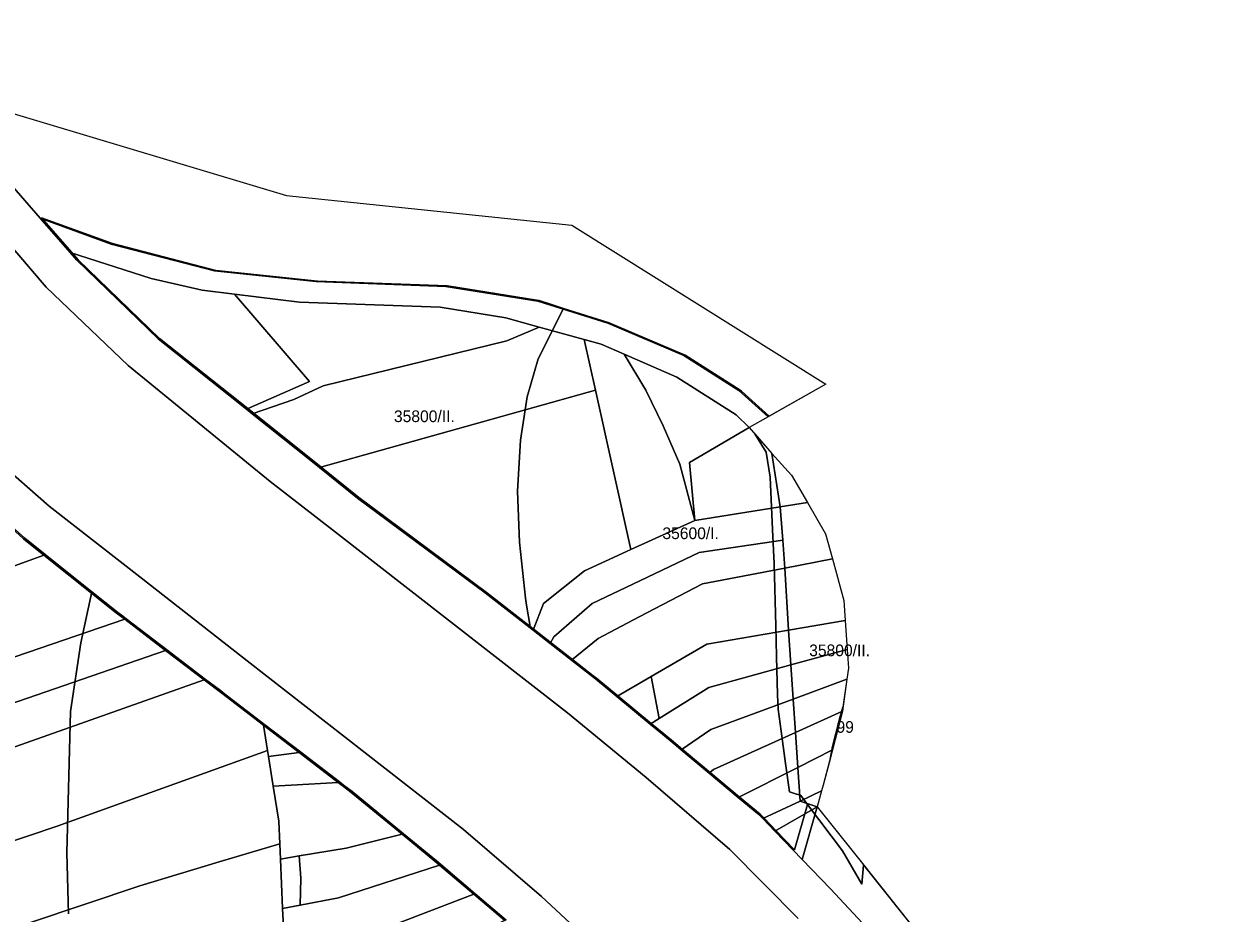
# Model space of a CAD drawing. Extents: x -535894 to -532834, y -1165802 to -1163645.
# Drawn here: x -533625 to -533117, y -1164507 to -1164127 of the extents above; entities that cross this region are included whole.
import ezdxf

# ---------------------------------------------------------------- set-up
doc = ezdxf.new("R2010")
doc.units = 0
for name, color, linetype in [('95560013', 7, 'Continuous'), ('95610013', 7, 'Continuous'), ('95630013', 7, 'Continuous'), ('95640013', 7, 'Continuous'), ('95660013', 7, 'Continuous')]:
    doc.layers.add(name, color=color, linetype=linetype)

msp = doc.modelspace()

# ---------------------------------------------------------------- linework, layer by layer
at = {"layer": '95560013'}
for points in [[(-533605.59, -1164224.96), (-533571.03, -1164236.07), (-533549.12, -1164240.98), (-533535.33, -1164242.69), (-533503.3, -1164280.07), (-533530.25, -1164291.87), (-533567.95, -1164261.82), (-533602.74, -1164228.22)], [(-533507.55, -1164246.14), (-533447.47, -1164248.27), (-533419.39, -1164252.85), (-533405.05, -1164256.81), (-533418.99, -1164262.66), (-533497.49, -1164281.99), (-533509.99, -1164287.71), (-533527.78, -1164293.84), (-533530.25, -1164291.87), (-533503.3, -1164280.07), (-533535.33, -1164242.69)], [(-533385.83, -1164262.11), (-533381.03, -1164283.8), (-533498.95, -1164316.9), (-533508.97, -1164308.83), (-533527.78, -1164293.84), (-533509.99, -1164287.71), (-533497.49, -1164281.99), (-533418.99, -1164262.66), (-533405.05, -1164256.81)], [(-533378.64, -1164264.1), (-533368.79, -1164268.38), (-533359.57, -1164283.78), (-533352.12, -1164299.01), (-533345.01, -1164315.49), (-533338.55, -1164339.54), (-533365.92, -1164351.97), (-533381.03, -1164283.8), (-533385.83, -1164262.11)], [(-533346.28, -1164278.18), (-533320.95, -1164294.31), (-533315.38, -1164299.76), (-533340.84, -1164314.67), (-533338.55, -1164339.54), (-533345.01, -1164315.49), (-533352.12, -1164299.01), (-533359.57, -1164283.78), (-533368.79, -1164268.38)], [(-533498.95, -1164316.9), (-533381.03, -1164283.8), (-533365.92, -1164351.97), (-533367.81, -1164352.83), (-533385.8, -1164361), (-533403.21, -1164375.02), (-533407.7, -1164386.45), (-533428.16, -1164370.44), (-533482.76, -1164329.92)], [(-533305.71, -1164310.91), (-533302.09, -1164333.74), (-533338.55, -1164339.54), (-533340.84, -1164314.67), (-533315.38, -1164299.76)], [(-533305.71, -1164310.91), (-533297.21, -1164320.14), (-533290.4, -1164331.87), (-533302.09, -1164333.74)], [(-533338.55, -1164339.54), (-533302.09, -1164333.74), (-533300.97, -1164347.97), (-533336.72, -1164353.24), (-533365.08, -1164366.74), (-533382.4, -1164374.97), (-533398.87, -1164389.28), (-533400.38, -1164392.18), (-533407.7, -1164386.45), (-533403.21, -1164375.02), (-533385.8, -1164361), (-533367.81, -1164352.83), (-533365.92, -1164351.97)], [(-533302.09, -1164333.74), (-533290.4, -1164331.87), (-533282.74, -1164345.28), (-533279.76, -1164355.99), (-533300.16, -1164359.88), (-533300.97, -1164347.97)], [(-533632.43, -1164341.14), (-533625.55, -1164347.3), (-533616.81, -1164354.28), (-533723.42, -1164393.06), (-533771.52, -1164411.45), (-533810.55, -1164423.74), (-533962.73, -1164479.54), (-533965.5, -1164468.47), (-533967.42, -1164462.17), (-533868.12, -1164425.2)], [(-533336.72, -1164353.24), (-533300.97, -1164347.97), (-533300.16, -1164359.88), (-533335.3, -1164366.6), (-533362.32, -1164380.78), (-533379.89, -1164389.99), (-533391.36, -1164399.24), (-533400.38, -1164392.18), (-533398.87, -1164389.28), (-533382.4, -1164374.97), (-533365.08, -1164366.74)], [(-533616.81, -1164354.28), (-533585.87, -1164379.01), (-533582.28, -1164381.75), (-533655.23, -1164406.66), (-533798.86, -1164459.07), (-533954.44, -1164514.16), (-533955.24, -1164509.41), (-533962.73, -1164479.54), (-533810.55, -1164423.74), (-533771.52, -1164411.45), (-533723.42, -1164393.06)], [(-533335.3, -1164366.6), (-533300.16, -1164359.88), (-533298.54, -1164386.42), (-533333.5, -1164392.41), (-533357.3, -1164406.29), (-533371.94, -1164414.84), (-533381.09, -1164407.28), (-533391.36, -1164399.24), (-533379.89, -1164389.99), (-533362.32, -1164380.78)], [(-533300.16, -1164359.88), (-533279.76, -1164355.99), (-533274.89, -1164373.76), (-533274.29, -1164382.26), (-533298.54, -1164386.42)], [(-533582.28, -1164381.75), (-533564.8, -1164395.06), (-533671.49, -1164431.9), (-533847.42, -1164496.13), (-533951.43, -1164531.95), (-533954.44, -1164514.16), (-533798.86, -1164459.07), (-533655.23, -1164406.66)], [(-533298.54, -1164386.42), (-533274.29, -1164382.26), (-533273.41, -1164394.65), (-533297.5, -1164401.27)], [(-533333.5, -1164392.41), (-533298.54, -1164386.42), (-533297.5, -1164401.27), (-533332.56, -1164410.91), (-533353.78, -1164424.22), (-533357.3, -1164406.29)], [(-533564.8, -1164395.06), (-533548.26, -1164407.66), (-533732.91, -1164473.02), (-533829.26, -1164508.78), (-533948.58, -1164548.78), (-533951.43, -1164531.95), (-533847.42, -1164496.13), (-533671.49, -1164431.9)], [(-533297.5, -1164401.27), (-533273.41, -1164394.65), (-533272.85, -1164402.66), (-533273.53, -1164407.35), (-533296.57, -1164415.9)], [(-533332.56, -1164410.91), (-533297.5, -1164401.27), (-533296.57, -1164415.9), (-533331.75, -1164428.95), (-533344.43, -1164437.59), (-533347.48, -1164435.05), (-533352.45, -1164430.94), (-533357.65, -1164426.65), (-533353.78, -1164424.22)], [(-533371.94, -1164414.84), (-533357.3, -1164406.29), (-533353.78, -1164424.22), (-533357.65, -1164426.65)], [(-533548.26, -1164407.66), (-533540.77, -1164413.38), (-533522.97, -1164427.03), (-533521.25, -1164437.9), (-533611.16, -1164470.19), (-533698.34, -1164499.57), (-533834.24, -1164549.38), (-533941.27, -1164585.42), (-533948.58, -1164548.78), (-533829.26, -1164508.78), (-533732.91, -1164473.02)], [(-533296.57, -1164415.9), (-533273.53, -1164407.35), (-533275.5, -1164421.12), (-533295.61, -1164430.22)], [(-533331.75, -1164428.95), (-533296.57, -1164415.9), (-533295.61, -1164430.22), (-533330.63, -1164446.04), (-533332.48, -1164447.55), (-533344.43, -1164437.59)], [(-533295.61, -1164430.22), (-533275.5, -1164421.12), (-533279.71, -1164437.57), (-533294.57, -1164445.09)], [(-533521.25, -1164437.9), (-533522.97, -1164427.03), (-533507.65, -1164438.78), (-533520.85, -1164440.43)], [(-533295.61, -1164430.22), (-533294.57, -1164445.09), (-533320, -1164457.95), (-533332.48, -1164447.55), (-533330.63, -1164446.04)], [(-533520.85, -1164440.43), (-533518.84, -1164453.12), (-533516.47, -1164468.06), (-533516.03, -1164477.8), (-533541.84, -1164485.53), (-533575.81, -1164495.71), (-533694.14, -1164535.35), (-533849.54, -1164592.24), (-533906.52, -1164610.42), (-533945.61, -1164619.41), (-533941.56, -1164587.64), (-533941.27, -1164585.42), (-533834.24, -1164549.38), (-533698.34, -1164499.57), (-533611.16, -1164470.19), (-533521.25, -1164437.9)], [(-533520.85, -1164440.43), (-533507.65, -1164438.78), (-533491.1, -1164451.5), (-533511.14, -1164452.67), (-533518.84, -1164453.12)], [(-533294.57, -1164445.09), (-533279.71, -1164437.57), (-533283.68, -1164452.7), (-533284.39, -1164455.19), (-533293.51, -1164459.56)], [(-533320, -1164457.95), (-533294.57, -1164445.09), (-533293.51, -1164459.56), (-533309.57, -1164466.99), (-533311.26, -1164465.24)], [(-533511.14, -1164452.67), (-533491.1, -1164451.5), (-533489.36, -1164452.83), (-533485.66, -1164455.66), (-533463.74, -1164473.66), (-533487.58, -1164479.72), (-533507.75, -1164482.99), (-533515.75, -1164484.29), (-533516.03, -1164477.8), (-533516.47, -1164468.06), (-533518.84, -1164453.12)], [(-533293.51, -1164459.56), (-533284.39, -1164455.19), (-533286.31, -1164461.99)], [(-533293.51, -1164459.56), (-533286.31, -1164461.99), (-533304.36, -1164472.39), (-533309.57, -1164466.99)], [(-533304.36, -1164472.39), (-533286.31, -1164461.99), (-533292.65, -1164484.53)], [(-533487.58, -1164479.72), (-533463.74, -1164473.66), (-533449.65, -1164485.24), (-533447.72, -1164486.86), (-533490.83, -1164500.89), (-533507.3, -1164504.04), (-533507.02, -1164492.54), (-533507.75, -1164482.99)], [(-533515.75, -1164484.29), (-533514.81, -1164505.48), (-533514.33, -1164516.05), (-533539.69, -1164523.07), (-533562.86, -1164529.48), (-533603.27, -1164541.66), (-533709.08, -1164577.64), (-533811.93, -1164617.39), (-533884.44, -1164639.64), (-533944.79, -1164655.52), (-533945.09, -1164650.16), (-533945.65, -1164648.02), (-533949.17, -1164647.34), (-533948.72, -1164643.84), (-533945.61, -1164619.41), (-533906.52, -1164610.42), (-533849.54, -1164592.24), (-533694.14, -1164535.35), (-533575.81, -1164495.71), (-533541.84, -1164485.53), (-533516.03, -1164477.8)], [(-533515.75, -1164484.29), (-533507.75, -1164482.99), (-533507.02, -1164492.54), (-533507.3, -1164504.04), (-533514.81, -1164505.48)], [(-533447.72, -1164486.86), (-533433.01, -1164499.36), (-533492.42, -1164522.13), (-533506.35, -1164525.6), (-533512.72, -1164527.18), (-533514.33, -1164516.05), (-533514.81, -1164505.48), (-533507.3, -1164504.04), (-533490.83, -1164500.89)], [(-533433.01, -1164499.36), (-533419.75, -1164510.6), (-533455.4, -1164526.78), (-533503.24, -1164545.82), (-533509.63, -1164548.37), (-533511.85, -1164533.08), (-533512.72, -1164527.18), (-533506.35, -1164525.6), (-533492.42, -1164522.13)]]:
    msp.add_lwpolyline(points, close=True, dxfattribs=at)
at = {"layer": '95610013'}
msp.add_lwpolyline([(-533588.04, -1164221.3), (-533543.95, -1164232.77), (-533500.45, -1164237.33), (-533445.02, -1164239.39), (-533405.72, -1164245.67), (-533375.76, -1164255.2), (-533343.32, -1164268.94), (-533319.79, -1164283.92), (-533307.29, -1164295.19), (-533315.38, -1164299.76), (-533320.95, -1164294.31), (-533346.28, -1164278.18), (-533368.79, -1164268.38), (-533378.64, -1164264.1), (-533385.83, -1164262.11), (-533405.05, -1164256.81), (-533419.39, -1164252.85), (-533447.47, -1164248.27), (-533507.55, -1164246.14), (-533535.33, -1164242.69), (-533549.12, -1164240.98), (-533571.03, -1164236.07), (-533605.59, -1164224.96), (-533618.43, -1164210.24)], close=True, dxfattribs=at)
at = {"layer": '95630013'}
msp.add_lwpolyline([(-533663.1, -1164153.72), (-533678.92, -1164127.1), (-533637.25, -1164163.31), (-533513.14, -1164200.59), (-533391.15, -1164213.21), (-533282.63, -1164281.27), (-533307.29, -1164295.19), (-533319.79, -1164283.92), (-533343.32, -1164268.94), (-533375.76, -1164255.2), (-533405.72, -1164245.67), (-533445.02, -1164239.39), (-533500.45, -1164237.33), (-533543.95, -1164232.77), (-533588.04, -1164221.3), (-533618.43, -1164210.24), (-533640.06, -1164185.46)], close=True, dxfattribs=at)
for points in [[(-533652.75, -1164196.64), (-533615.89, -1164239.81), (-533580.88, -1164273.2), (-533520.08, -1164322.87), (-533493.52, -1164343.51), (-533393.01, -1164421.73), (-533359.31, -1164449.39), (-533323.6, -1164480.19), (-533294.45, -1164509.67)], [(-533365.03, -1164536.67), (-533404.17, -1164500.26), (-533437.52, -1164471.63), (-533529.97, -1164399.56), (-533574.57, -1164364.55), (-533614.65, -1164333.34), (-533637.12, -1164313.74)]]:
    msp.add_lwpolyline(points, dxfattribs=at)
at = {"layer": '95640013'}
for points in [[(-533640.06, -1164185.46), (-533618.43, -1164210.24), (-533605.59, -1164224.96), (-533602.74, -1164228.22), (-533567.95, -1164261.82), (-533530.25, -1164291.87), (-533527.78, -1164293.84), (-533508.97, -1164308.83), (-533498.95, -1164316.9), (-533482.76, -1164329.92), (-533428.16, -1164370.44), (-533407.7, -1164386.45), (-533400.38, -1164392.18), (-533391.36, -1164399.24), (-533381.09, -1164407.28), (-533371.94, -1164414.84), (-533357.65, -1164426.65), (-533352.45, -1164430.94), (-533347.48, -1164435.05), (-533344.43, -1164437.59), (-533332.48, -1164447.55), (-533320, -1164457.95), (-533311.26, -1164465.24), (-533309.57, -1164466.99), (-533304.36, -1164472.39), (-533292.65, -1164484.53), (-533280.62, -1164497.03), (-533235.68, -1164545.17)], [(-533294.45, -1164509.67), (-533323.6, -1164480.19), (-533359.31, -1164449.39), (-533393.01, -1164421.73), (-533493.52, -1164343.51), (-533520.08, -1164322.87), (-533580.88, -1164273.2), (-533615.89, -1164239.81), (-533652.75, -1164196.64)], [(-533637.12, -1164313.74), (-533614.65, -1164333.34), (-533574.57, -1164364.55), (-533529.97, -1164399.56), (-533437.52, -1164471.63), (-533404.17, -1164500.26), (-533365.03, -1164536.67)], [(-533419.75, -1164510.6), (-533433.01, -1164499.36), (-533447.72, -1164486.86), (-533449.65, -1164485.24), (-533463.74, -1164473.66), (-533485.66, -1164455.66), (-533489.36, -1164452.83), (-533491.1, -1164451.5), (-533507.65, -1164438.78), (-533522.97, -1164427.03), (-533540.77, -1164413.38), (-533548.26, -1164407.66), (-533564.8, -1164395.06), (-533582.28, -1164381.75), (-533585.87, -1164379.01), (-533616.81, -1164354.28), (-533625.55, -1164347.3)]]:
    msp.add_lwpolyline(points, dxfattribs=at)
msp.add_lwpolyline([(-533286.31, -1164461.99), (-533266.97, -1164486.26), (-533227.22, -1164536.15), (-533217.69, -1164548.05), (-533212.4, -1164563.33), (-533202.85, -1164583.35), (-533177.04, -1164603.82), (-533165.64, -1164607.65), (-533127.31, -1164620.51), (-533116.98, -1164633.6), (-533177.92, -1164613.75), (-533205.86, -1164580.27), (-533235.68, -1164545.17), (-533280.62, -1164497.03), (-533292.65, -1164484.53)], close=True, dxfattribs=at)
at = {"layer": '95660013'}
for points in [[(-533637.25, -1164163.31), (-533513.14, -1164200.59), (-533391.15, -1164213.21), (-533282.63, -1164281.27), (-533306.824, -1164294.927), (-533318.689, -1164284.23), (-533319.215, -1164283.756), (-533342.741, -1164268.774), (-533364.507, -1164259.557), (-533375.189, -1164255.034), (-533394.693, -1164248.828), (-533399.775, -1164247.211), (-533405.147, -1164245.502), (-533406.3, -1164245.318), (-533439.891, -1164239.947), (-533444.45, -1164239.218), (-533499.877, -1164237.155), (-533543.375, -1164232.587), (-533587.465, -1164221.122), (-533617.855, -1164210.054), (-533605.015, -1164224.773), (-533602.168, -1164228.037), (-533567.381, -1164261.637), (-533529.675, -1164291.688), (-533508.391, -1164308.653), (-533498.372, -1164316.72), (-533482.183, -1164329.739), (-533427.582, -1164370.261), (-533408.962, -1164384.837), (-533407.119, -1164386.28), (-533399.797, -1164392.005), (-533390.783, -1164399.064), (-533382.023, -1164405.923), (-533380.51, -1164407.108), (-533371.36, -1164414.666), (-533357.069, -1164426.477), (-533351.871, -1164430.767), (-533346.896, -1164434.883), (-533343.848, -1164437.415), (-533331.897, -1164447.377), (-533319.421, -1164457.779), (-533310.674, -1164465.071), (-533308.987, -1164466.818), (-533303.773, -1164472.227), (-533295.97, -1164480.319), (-533290.471, -1164460.99), (-533275.469, -1164480.798), (-533267.177, -1164495.052), (-533266.414, -1164486.957), (-533227.22, -1164536.15)], [(-533631.849, -1164340.954), (-533624.977, -1164347.111), (-533616.237, -1164354.099), (-533596.317, -1164370.019), (-533601.09, -1164391.8), (-533605.391, -1164421.259), (-533606.98, -1164481.63), (-533606.34, -1164507.75)], [(-533419.163, -1164510.425), (-533432.421, -1164499.181), (-533447.139, -1164486.688), (-533449.061, -1164485.066), (-533463.157, -1164473.487), (-533485.08, -1164455.484), (-533488.779, -1164452.648), (-533490.512, -1164451.319), (-533507.067, -1164438.601), (-533522.39, -1164426.846), (-533540.189, -1164413.195), (-533541.383, -1164412.285), (-533547.683, -1164407.482), (-533564.22, -1164394.878), (-533581.704, -1164381.564), (-533583.679, -1164380.059), (-533585.293, -1164378.83), (-533596.317, -1164370.019), (-533616.237, -1164354.099), (-533624.977, -1164347.111), (-533631.849, -1164340.954)], [(-533606.34, -1164507.75), (-533606.98, -1164481.63), (-533605.391, -1164421.259), (-533601.09, -1164391.8), (-533596.317, -1164370.019), (-533585.293, -1164378.83), (-533583.679, -1164380.059), (-533581.704, -1164381.564), (-533564.22, -1164394.878), (-533547.683, -1164407.482), (-533541.383, -1164412.285), (-533540.189, -1164413.195), (-533522.39, -1164426.846), (-533507.067, -1164438.601), (-533490.512, -1164451.319), (-533488.779, -1164452.648), (-533485.08, -1164455.484), (-533463.157, -1164473.487), (-533449.061, -1164485.066), (-533447.139, -1164486.688), (-533432.421, -1164499.181), (-533419.163, -1164510.425)]]:
    msp.add_lwpolyline(points, dxfattribs=at)
for points in [[(-533394.693, -1164248.828), (-533405.49, -1164270.43), (-533410.27, -1164286.67), (-533413.14, -1164305.15), (-533414.411, -1164326.97), (-533413.524, -1164348.809), (-533410.92, -1164372.686), (-533410.59, -1164375.71), (-533408.962, -1164384.837), (-533427.582, -1164370.261), (-533482.183, -1164329.739), (-533498.372, -1164316.72), (-533508.391, -1164308.653), (-533529.675, -1164291.688), (-533567.381, -1164261.637), (-533602.168, -1164228.037), (-533605.015, -1164224.773), (-533617.855, -1164210.054), (-533587.465, -1164221.122), (-533543.375, -1164232.587), (-533499.877, -1164237.155), (-533444.45, -1164239.218), (-533439.891, -1164239.947), (-533406.3, -1164245.318), (-533405.147, -1164245.502), (-533399.775, -1164247.211)], [(-533306.824, -1164294.927), (-533307.29, -1164295.19), (-533315.38, -1164299.76), (-533312.979, -1164302.529), (-533308.125, -1164310.332), (-533306.426, -1164321.014), (-533305.972, -1164330.592), (-533305.373, -1164343.305), (-533304.675, -1164358.111), (-533303.964, -1164384.558), (-533303.616, -1164397.625), (-533303.177, -1164414.033), (-533303.014, -1164420.167), (-533301.728, -1164429.587), (-533299.828, -1164443.44), (-533298.173, -1164455.526), (-533296.377, -1164456.108), (-533293.202, -1164457.145), (-533290.471, -1164460.99), (-533295.97, -1164480.319), (-533303.773, -1164472.227), (-533308.987, -1164466.818), (-533310.674, -1164465.071), (-533319.421, -1164457.779), (-533331.897, -1164447.377), (-533343.848, -1164437.415), (-533346.896, -1164434.883), (-533351.871, -1164430.767), (-533357.069, -1164426.477), (-533371.36, -1164414.666), (-533380.51, -1164407.108), (-533382.023, -1164405.923), (-533390.783, -1164399.064), (-533399.797, -1164392.005), (-533407.119, -1164386.28), (-533408.962, -1164384.837), (-533410.59, -1164375.71), (-533410.92, -1164372.686), (-533413.524, -1164348.809), (-533414.411, -1164326.97), (-533413.14, -1164305.15), (-533410.27, -1164286.67), (-533405.49, -1164270.43), (-533394.693, -1164248.828), (-533375.189, -1164255.034), (-533364.507, -1164259.557), (-533342.741, -1164268.774), (-533319.215, -1164283.756), (-533318.689, -1164284.23)], [(-533275.249, -1164419.367), (-533276.425, -1164423.386), (-533278.23, -1164430.56), (-533279.661, -1164436.105), (-533280.772, -1164441.617), (-533283.68, -1164452.7), (-533284.39, -1164455.19), (-533286.31, -1164461.99), (-533266.97, -1164486.26), (-533266.414, -1164486.957), (-533267.177, -1164495.052), (-533275.469, -1164480.798), (-533290.471, -1164460.99), (-533293.202, -1164457.145), (-533296.377, -1164456.108), (-533298.173, -1164455.526), (-533299.828, -1164443.44), (-533301.728, -1164429.587), (-533303.014, -1164420.167), (-533303.177, -1164414.033), (-533303.616, -1164397.625), (-533303.964, -1164384.558), (-533304.675, -1164358.111), (-533305.373, -1164343.305), (-533305.972, -1164330.592), (-533306.426, -1164321.014), (-533308.125, -1164310.332), (-533312.979, -1164302.529), (-533305.71, -1164310.91), (-533297.21, -1164320.14), (-533290.4, -1164331.87), (-533282.74, -1164345.28), (-533279.76, -1164355.99), (-533274.89, -1164373.76), (-533274.29, -1164382.26), (-533273.41, -1164394.65), (-533272.85, -1164402.66), (-533273.53, -1164407.35)], [(-533279.71, -1164437.57), (-533280.772, -1164441.617), (-533279.661, -1164436.105), (-533278.23, -1164430.56), (-533276.425, -1164423.386), (-533275.249, -1164419.367), (-533275.5, -1164421.12)]]:
    msp.add_lwpolyline(points, close=True, dxfattribs=at)

# ---------------------------------------------------------------- texts
for s, p in [('35800/II.', (-533467.198, -1164297.446)), ('35600/I.', (-533352.441, -1164347.482)), ('35800/II.', (-533289.697, -1164397.557)), ('99', (-533278.011, -1164430.309))]:
    msp.add_text(s, height=5, rotation=0, dxfattribs=at).set_placement(p)

doc.saveas('drawing.dxf')
